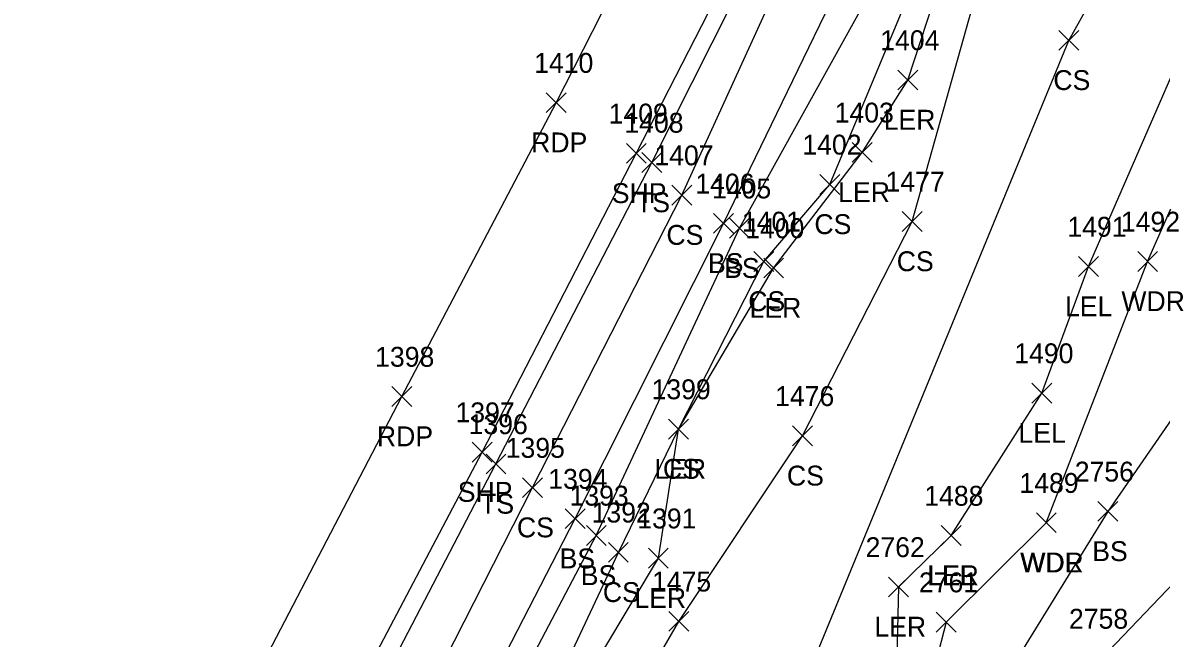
# Model space of a CAD drawing. Extents: x 1483143 to 1488182, y 802902 to 807581.
# Drawn here: x 1487426.2 to 1487540.6, y 805594.5 to 805656.4 of the extents above; entities that cross this region are included whole.
import ezdxf

# ---------------------------------------------------------------- set-up
doc = ezdxf.new("R2010")
doc.units = 0
for name, color, linetype in [('L_A', 7, 'Continuous'), ('L_I', 7, 'Continuous'), ('L_TIC', 7, 'Continuous'), ('LARO', 7, 'Continuous'), ('LAWA', 7, 'Continuous'), ('LELB', 7, 'Continuous'), ('P_A', 7, 'Continuous'), ('P_I', 7, 'Continuous'), ('P_TIC', 7, 'Continuous'), ('PET', 7, 'Continuous'), ('PSP', 7, 'Continuous')]:
    doc.layers.add(name, color=color, linetype=linetype)

msp = doc.modelspace()

# ---------------------------------------------------------------- linework, layer by layer
at = {"layer": 'L_TIC'}
for points in [[(1487530.36, 805653.66), (1487532.36, 805655.66)], [(1487532.36, 805653.66), (1487530.36, 805655.66)], [(1487514.16, 805649.67), (1487516.16, 805651.67)], [(1487516.16, 805649.67), (1487514.16, 805651.67)], [(1487509.58, 805642.39), (1487511.58, 805644.39)], [(1487511.58, 805642.39), (1487509.58, 805644.39)], [(1487488.43, 805641.37), (1487490.43, 805643.37)], [(1487490.43, 805641.37), (1487488.43, 805643.37)], [(1487506.33, 805639.17), (1487508.33, 805641.17)], [(1487508.33, 805639.17), (1487506.33, 805641.17)], [(1487491.45, 805638.09), (1487493.45, 805640.09)], [(1487493.45, 805638.09), (1487491.45, 805640.09)], [(1487495.63, 805635.25), (1487497.63, 805637.25)], [(1487497.63, 805635.25), (1487495.63, 805637.25)], [(1487514.61, 805635.44), (1487516.61, 805637.44)], [(1487516.61, 805635.44), (1487514.61, 805637.44)], [(1487497.25, 805634.76), (1487499.25, 805636.76)], [(1487499.25, 805634.76), (1487497.25, 805636.76)], [(1487499.68, 805631.42), (1487501.68, 805633.42)], [(1487501.68, 805631.42), (1487499.68, 805633.42)], [(1487538.28, 805631.42), (1487540.28, 805633.42)], [(1487540.28, 805631.42), (1487538.28, 805633.42)], [(1487500.67, 805630.76), (1487502.67, 805632.76)], [(1487502.67, 805630.76), (1487500.67, 805632.76)], [(1487532.33, 805630.91), (1487534.33, 805632.91)], [(1487534.33, 805630.91), (1487532.33, 805632.91)], [(1487527.65, 805618.18), (1487529.65, 805620.18)], [(1487529.65, 805618.18), (1487527.65, 805620.18)], [(1487491.1, 805614.56), (1487493.1, 805616.56)], [(1487493.1, 805614.56), (1487491.1, 805616.56)], [(1487491.1, 805614.56), (1487493.1, 805616.56)], [(1487493.1, 805614.56), (1487491.1, 805616.56)], [(1487503.57, 805613.88), (1487505.57, 805615.88)], [(1487505.57, 805613.88), (1487503.57, 805615.88)], [(1487472.75, 805611.05), (1487474.75, 805613.05)], [(1487474.75, 805611.05), (1487472.75, 805613.05)], [(1487476.42, 805608.67), (1487478.42, 805610.67)], [(1487478.42, 805608.67), (1487476.42, 805610.67)], [(1487534.27, 805606.28), (1487536.27, 805608.28)], [(1487536.27, 805606.28), (1487534.27, 805608.28)], [(1487480.71, 805605.55), (1487482.71, 805607.55)], [(1487482.71, 805605.55), (1487480.71, 805607.55)], [(1487528.09, 805605.14), (1487530.09, 805607.14)], [(1487530.09, 805605.14), (1487528.09, 805607.14)], [(1487528.09, 805605.14), (1487530.09, 805607.14)], [(1487530.09, 805605.14), (1487528.09, 805607.14)], [(1487482.84, 805603.86), (1487484.84, 805605.86)], [(1487484.84, 805603.86), (1487482.84, 805605.86)], [(1487518.52, 805603.85), (1487520.52, 805605.85)], [(1487520.52, 805603.85), (1487518.52, 805605.85)], [(1487518.52, 805603.85), (1487520.52, 805605.85)], [(1487520.52, 805603.85), (1487518.52, 805605.85)], [(1487485.06, 805602.16), (1487487.06, 805604.16)], [(1487487.06, 805602.16), (1487485.06, 805604.16)], [(1487489.08, 805601.57), (1487491.08, 805603.57)], [(1487491.08, 805601.57), (1487489.08, 805603.57)], [(1487513.22, 805598.68), (1487515.22, 805600.68)], [(1487515.22, 805598.68), (1487513.22, 805600.68)], [(1487491.13, 805595.22), (1487493.13, 805597.22)], [(1487493.13, 805595.22), (1487491.13, 805597.22)], [(1487518.02, 805595.14), (1487520.02, 805597.14)], [(1487520.02, 805595.14), (1487518.02, 805597.14)]]:
    msp.add_lwpolyline(points, dxfattribs=at)
at = {"layer": 'LARO'}
for points in [[(1487519.52, 805604.85), (1487528.65, 805619.18), (1487533.33, 805631.91), (1487543.2, 805654.53), (1487555.05, 805678.36), (1487574.29, 805702.91), (1487587.86, 805730.92), (1487594.38, 805745.99), (1487602.81, 805747.66), (1487615.34, 805754.21), (1487619.89, 805765.57), (1487618.06, 805788.02), (1487632.01, 805808.09), (1487647.52, 805827.2), (1487662.05, 805847.87), (1487673.84, 805865.59), (1487680.96, 805879.63), (1487690.31, 805890.08), (1487695.82, 805899.7), (1487708.05, 805917.66), (1487714.11, 805946.66), (1487707.45, 805965.6), (1487711.43, 805989.94)], [(1487423.77, 805476.17), (1487448.72, 805522.61), (1487473.04, 805567.85), (1487480.6, 805581.28), (1487481.64, 805588.45), (1487490.08, 805602.57), (1487492.1, 805615.56), (1487501.67, 805631.76), (1487510.58, 805643.39), (1487515.16, 805650.67), (1487521.68, 805670.54)], [(1487553.51, 805539.5), (1487570.22, 805552.53), (1487590.58, 805565.95), (1487593.27, 805576.26), (1487589.04, 805592.63), (1487578.77, 805612.98), (1487577.04, 805623.26), (1487583.1, 805647.56), (1487579.43, 805649.82), (1487564.56, 805648.82), (1487556.92, 805624.92), (1487544.14, 805602.42), (1487534.63, 805592.48), (1487523.05, 805587.43), (1487515.17, 805575.06), (1487516.1, 805566.68), (1487507.05, 805566.31), (1487501.49, 805546.71), (1487498.24, 805522.63), (1487497.33, 805510.34), (1487498.95, 805499.29), (1487507.62, 805506.23)], [(1487514.22, 805599.68), (1487519.52, 805604.85)], [(1487514.22, 805599.68), (1487513.65, 805575.43), (1487516.1, 805566.68), (1487520.1, 805562.54), (1487515.33, 805545.58), (1487515.66, 805524.88), (1487507.62, 805506.23)]]:
    msp.add_lwpolyline(points, dxfattribs=at)
at = {"layer": 'LAWA'}
for points in [[(1487529.09, 805606.14), (1487539.28, 805632.42), (1487550.45, 805657.72), (1487555.05, 805678.36), (1487580.53, 805701.65), (1487594.42, 805727.14), (1487615.34, 805754.21), (1487623.26, 805766.5), (1487630.87, 805783.06), (1487637.96, 805804.22), (1487654.61, 805825.46), (1487661.73, 805840.49), (1487675.69, 805864.29), (1487683.26, 805876.52), (1487690.31, 805890.08), (1487698.57, 805894.98), (1487712.71, 805915.11), (1487715.76, 805935.97), (1487722.85, 805947.47), (1487721.66, 805955.35), (1487715.74, 805966.94), (1487726.15, 805982.46)], [(1487519.02, 805596.14), (1487529.09, 805606.14)], [(1487519.02, 805596.14), (1487513.65, 805575.43), (1487507.05, 805566.31), (1487494, 805544.66)]]:
    msp.add_lwpolyline(points, dxfattribs=at)
at = {"layer": 'LELB'}
for points in [[(1487406.66, 805485.41), (1487431.45, 805531.24), (1487454.84, 805575.74), (1487473.75, 805612.05), (1487489.43, 805642.37), (1487507.64, 805678.53), (1487524.82, 805711.39), (1487541.86, 805746.09), (1487557.67, 805776.44), (1487575.49, 805812.01), (1487597.52, 805857.93), (1487620.62, 805906.82), (1487641.85, 805951.94), (1487662.18, 805996.35), (1487684.09, 806043.93), (1487694.42, 806066.95), (1487726.58, 806140.7), (1487745.85, 806185.55), (1487769.04, 806237.65), (1487788.58, 806284.85), (1487808.3, 806333.26), (1487827.52, 806379.6), (1487850.09, 806437.73)], [(1487410.04, 805483.24), (1487436.07, 805529.53), (1487459.78, 805575.03), (1487477.42, 805609.67), (1487492.45, 805639.09), (1487509.86, 805677.27), (1487528.68, 805708.85), (1487545.3, 805744.17), (1487561.79, 805774.32), (1487579.7, 805810.21), (1487602.04, 805856.31), (1487624.97, 805905.57), (1487645.72, 805950.02), (1487667.21, 805993.1), (1487687.16, 806043.23), (1487699.2, 806065.16), (1487730.65, 806138.87), (1487749.96, 806183.58), (1487772.93, 806235.17), (1487792.36, 806283.08), (1487812.9, 806331.5), (1487831.61, 806378.23), (1487855.61, 806436.65)], [(1487413.83, 805481.53), (1487440.22, 805526.89), (1487464.36, 805572.85), (1487481.71, 805606.55), (1487496.63, 805636.25), (1487514.9, 805673.97), (1487535.8, 805705.94), (1487549.07, 805741.59), (1487566.17, 805772.22), (1487583.99, 805807.69), (1487605.26, 805855.28), (1487629.33, 805903.01), (1487650.26, 805948.76), (1487670.48, 805991.25), (1487690.28, 806041.74), (1487702.22, 806061.37), (1487704.47, 806066.39), (1487735.28, 806136.71), (1487754, 806182.42), (1487776.55, 806233.47), (1487796.75, 806281.41), (1487816.88, 806330.25), (1487835.19, 806376.59), (1487859.78, 806434.97)], [(1487417, 805480.8), (1487442.28, 805525.8), (1487466.47, 805571.82), (1487483.84, 805604.86), (1487498.25, 805635.76), (1487518.24, 805671.86), (1487538.47, 805704.77), (1487552.2, 805739.67), (1487568.17, 805771.84), (1487585.97, 805806.76), (1487609.39, 805853.47), (1487632.34, 805900.81), (1487653.02, 805947.32), (1487672.59, 805990.01), (1487694.92, 806039.27), (1487707.45, 806059.25), (1487710.05, 806064.3), (1487737.97, 806135.43), (1487757.4, 806181.42), (1487778.76, 806231.94), (1487799.97, 806279.97), (1487818.92, 806329.91), (1487837.5, 806376), (1487863.45, 806433.38)], [(1487428.48, 805479.23), (1487445.24, 805504.83), (1487451, 805517.25), (1487457.88, 805528.42), (1487471.74, 805554.31), (1487483.64, 805581.5), (1487492.13, 805596.22), (1487504.57, 805614.88), (1487515.61, 805636.44), (1487523.33, 805664.03), (1487527.1, 805668), (1487534.05, 805680.73), (1487538.75, 805686.85), (1487544.76, 805692.45), (1487548.74, 805693.28), (1487553.89, 805708.06), (1487558.5, 805723.21), (1487562.96, 805732.39), (1487569.7, 805746.23), (1487572.43, 805748.36), (1487588.97, 805765.58), (1487591.12, 805760.32), (1487603.32, 805759.56)], [(1487438.06, 805486.56), (1487449.51, 805502.69), (1487463.77, 805527.56), (1487473.75, 805548.89), (1487480.23, 805555.64), (1487489.68, 805553.31), (1487531.36, 805654.66), (1487538.66, 805667.76), (1487544.44, 805685.95), (1487547.35, 805690.53), (1487553.51, 805690.65), (1487551.83, 805696.06), (1487556.39, 805700.08), (1487558.02, 805713.74), (1487569.17, 805725.52), (1487574.82, 805736.37), (1487607.32, 805758.13)], [(1487199.3, 805080.96), (1487209.02, 805107.06), (1487224.53, 805127.21), (1487240.95, 805152.24), (1487249.95, 805171.94), (1487269.65, 805210.5), (1487285.86, 805237.33), (1487303.36, 805267.84), (1487322.25, 805302.17), (1487347.45, 805347.07), (1487376.58, 805390.13), (1487398.58, 805433.78), (1487419.88, 805479.75), (1487445.41, 805524.09), (1487470.45, 805569.86), (1487486.06, 805603.16), (1487492.1, 805615.56), (1487500.68, 805632.42), (1487507.33, 805640.17), (1487520.3, 805671.34), (1487528.77, 805686.31), (1487539.17, 805698.49)], [(1487564.52, 805673.97), (1487563.22, 805648.26), (1487549.74, 805628.2), (1487535.27, 805607.28), (1487523.05, 805587.43), (1487520.1, 805562.54), (1487524.46, 805543.15), (1487523.95, 805516.73)]]:
    msp.add_lwpolyline(points, dxfattribs=at)
at = {"layer": 'P_TIC'}
for points in [[(1487478.8, 805647.39), (1487480.8, 805649.39)], [(1487480.8, 805647.39), (1487478.8, 805649.39)], [(1487486.86, 805642.29), (1487488.86, 805644.29)], [(1487488.86, 805642.29), (1487486.86, 805644.29)], [(1487463.29, 805617.83), (1487465.29, 805619.83)], [(1487465.29, 805617.83), (1487463.29, 805619.83)], [(1487471.37, 805612.24), (1487473.37, 805614.24)], [(1487473.37, 805612.24), (1487471.37, 805614.24)]]:
    msp.add_lwpolyline(points, dxfattribs=at)
at = {"layer": 'PET'}
msp.add_lwpolyline([(1487396.33, 805490.41), (1487421.9, 805537.94), (1487444.13, 805580.16), (1487464.29, 805618.83), (1487479.8, 805648.39), (1487498.08, 805684.27), (1487514.57, 805717.15), (1487530.55, 805749.06), (1487547.16, 805782.47), (1487564.33, 805817.54), (1487585.71, 805863.32), (1487608.89, 805911.38), (1487630.35, 805956.68), (1487651.22, 806001.25), (1487672.63, 806048.33), (1487683.65, 806072.29), (1487715.61, 806144.47), (1487735.35, 806190.47), (1487757.48, 806241.03), (1487777.65, 806289.15), (1487798.25, 806337.46), (1487817.05, 806384.04), (1487839.67, 806441.4)], dxfattribs=at)
at = {"layer": 'PSP'}
msp.add_lwpolyline([(1487405.03, 805486.21), (1487429.8, 805532.42), (1487452.92, 805576.31), (1487472.37, 805613.24), (1487487.86, 805643.29), (1487506.35, 805679.4), (1487523.34, 805712.45), (1487540.38, 805746.64), (1487556.03, 805777.85), (1487573.44, 805813.27), (1487595.34, 805859.04), (1487618.37, 805906.67), (1487640.09, 805952.42), (1487660.18, 805997.21), (1487682.38, 806044.71), (1487693.04, 806068.56), (1487725.12, 806141.19), (1487744.39, 806185.87), (1487766.81, 806238.55), (1487786.8, 806285.64), (1487806.77, 806333.93), (1487825.55, 806380.21), (1487847.81, 806437.56)], dxfattribs=at)

# ---------------------------------------------------------------- texts
at = {"layer": 'L_A'}
for s, p in [('CS', (1487529.8, 805649.66)), ('LER', (1487512.74, 805645.67)), ('LER', (1487508.16, 805638.39)), ('TS', (1487487.84, 805637.37)), ('CS', (1487505.77, 805635.17)), ('CS', (1487490.89, 805634.09)), ('CS', (1487514.05, 805631.44)), ('BS', (1487495.07, 805631.25)), ('BS', (1487496.69, 805630.76)), ('CS', (1487499.12, 805627.42)), ('LEL', (1487530.97, 805626.91)), ('WDR', (1487536.64, 805627.42)), ('LER', (1487499.25, 805626.76)), ('LEL', (1487526.29, 805614.18)), ('LER', (1487489.68, 805610.56)), ('CS', (1487490.54, 805610.56)), ('CS', (1487503.01, 805609.88)), ('TS', (1487472.16, 805607.05)), ('CS', (1487475.86, 805604.67)), ('BS', (1487533.71, 805602.28)), ('BS', (1487480.15, 805601.55)), ('WDR', (1487526.45, 805601.14)), ('WDL', (1487526.5, 805601.14)), ('BS', (1487482.28, 805599.86)), ('LER', (1487517.1, 805599.85)), ('LEL', (1487517.15, 805599.85)), ('CS', (1487484.5, 805598.16)), ('LER', (1487487.67, 805597.57)), ('LER', (1487511.8, 805594.68))]:
    msp.add_text(s, height=2, dxfattribs=at).set_placement(p)
at = {"layer": 'L_I'}
for s, p in [('1404', (1487512.39, 805653.67)), ('1403', (1487507.81, 805646.39)), ('1408', (1487486.66, 805645.37)), ('1402', (1487504.56, 805643.17)), ('1407', (1487489.68, 805642.09)), ('1477', (1487512.92, 805639.44)), ('1406', (1487493.8, 805639.25)), ('1405', (1487495.48, 805638.76)), ('1401', (1487498.48, 805635.42)), ('1491', (1487531.21, 805634.91)), ('1492', (1487536.59, 805635.42)), ('1400', (1487498.81, 805634.76)), ('1490', (1487525.87, 805622.18)), ('1399', (1487489.4, 805618.56)), ('1399', (1487489.4, 805618.56)), ('1476', (1487501.82, 805617.88)), ('1396', (1487471, 805615.05)), ('1395', (1487474.73, 805612.67)), ('2756', (1487531.95, 805610.28)), ('1394', (1487479.01, 805609.55)), ('1489', (1487526.39, 805609.14)), ('1489', (1487526.39, 805609.14)), ('1393', (1487481.15, 805607.86)), ('1488', (1487516.82, 805607.85)), ('1488', (1487516.82, 805607.85)), ('1392', (1487483.37, 805606.16)), ('1391', (1487487.96, 805605.57)), ('2762', (1487510.92, 805602.68)), ('1475', (1487489.44, 805599.22)), ('2761', (1487516.28, 805599.14)), ('2758', (1487531.37, 805595.48)), ('2758', (1487531.37, 805595.48))]:
    msp.add_text(s, height=2, dxfattribs=at).set_placement(p)
at = {"layer": 'P_A'}
for s, p in [('RDP', (1487477.29, 805643.39)), ('SHP', (1487485.4, 805638.29)), ('RDP', (1487461.78, 805613.83)), ('SHP', (1487469.91, 805608.24))]:
    msp.add_text(s, height=2, dxfattribs=at).set_placement(p)
at = {"layer": 'P_I'}
for s, p in [('1410', (1487477.59, 805651.39)), ('1409', (1487485.08, 805646.29)), ('1398', (1487461.6, 805621.83)), ('1397', (1487469.68, 805616.24))]:
    msp.add_text(s, height=2, dxfattribs=at).set_placement(p)

doc.saveas('drawing.dxf')
